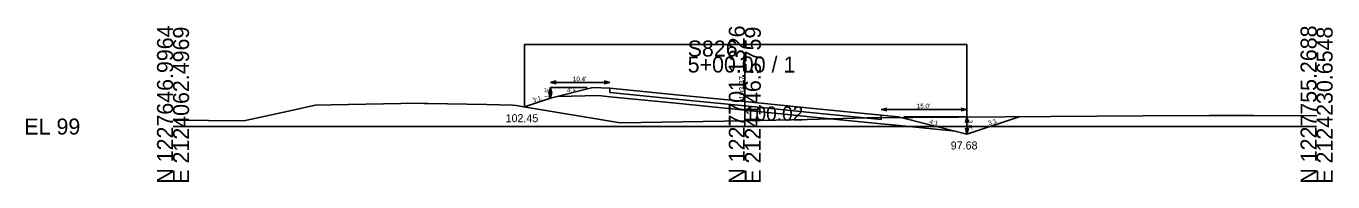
# Model space of a CAD drawing. Extents: x 2118382 to 2129610, y 1213030 to 1222578.
# Drawn here: x 2118381.9 to 2118610.4, y 1215530.1 to 1215557.4 of the extents above; entities that cross this region are included whole.
import ezdxf

# ---------------------------------------------------------------- set-up
doc = ezdxf.new("R2010")
doc.units = 0
for name, color, linetype in [('XS_CELL', 7, 'Continuous'), ('XS_M_DITCH', 7, 'Continuous'), ('XS_P_FINISHED_GRADE', 7, 'Continuous'), ('XS_P_FINISHED_GRADE_ELEV_TX', 7, 'Continuous'), ('XS_P_SUBGRADE_GRANULAR', 7, 'Continuous'), ('XS_P_SUBGRADE_PAVEMENT', 7, 'Continuous'), ('XS_P_TX_CLEARZONE', 7, 'Continuous'), ('XS_P_TX_DCH', 7, 'Continuous'), ('XS_P_TX_FS_BS', 7, 'Continuous'), ('XS_X_GROUND', 7, 'Continuous'), ('XS_X_GROUND_TX', 7, 'Continuous')]:
    doc.layers.add(name, color=color, linetype=linetype)

msp = doc.modelspace()

# ---------------------------------------------------------------- linework, layer by layer
at = {"layer": 'XS_CELL'}
for p, q in [((2118507.6, 1215539.8), (2118507.6, 1215552.06)), ((2118407.6, 1215539.8), (2118507.6, 1215539.8)), ((2118507.6, 1215539.8), (2118607.6, 1215539.8))]:
    msp.add_line(p, q, dxfattribs=at)
at = {"layer": 'XS_M_DITCH'}
for p, q in [((2118469.07, 1215543.26), (2118469.07, 1215554.17)), ((2118469.07, 1215554.17), (2118546.45, 1215554.17)), ((2118546.45, 1215554.17), (2118546.45, 1215538.49))]:
    msp.add_line(p, q, dxfattribs=at)
at = {"layer": 'XS_P_FINISHED_GRADE'}
for p, q in [((2118481.01, 1215546.62), (2118473.59, 1215544.76)), ((2118484.02, 1215546.53), (2118481.01, 1215546.62)), ((2118473.59, 1215544.76), (2118469.07, 1215543.26)), ((2118495.6, 1215545.37), (2118484.02, 1215546.53)), ((2118495.6, 1215545.37), (2118507.6, 1215544.17)), ((2118507.6, 1215544.17), (2118519.6, 1215542.97)), ((2118519.6, 1215542.97), (2118531.42, 1215541.79)), ((2118531.42, 1215541.79), (2118534.43, 1215541.49)), ((2118534.43, 1215541.49), (2118546.45, 1215538.49)), ((2118546.45, 1215538.49), (2118555.56, 1215541.52))]:
    msp.add_line(p, q, dxfattribs=at)
at = {"layer": 'XS_P_SUBGRADE_GRANULAR'}
for p, q in [((2118482.02, 1215545.23), (2118474.88, 1215545.08)), ((2118484.02, 1215545.03), (2118482.02, 1215545.23)), ((2118495.6, 1215543.87), (2118484.02, 1215545.03)), ((2118495.6, 1215543.87), (2118507.6, 1215542.67)), ((2118507.6, 1215542.67), (2118519.6, 1215541.47)), ((2118519.6, 1215541.47), (2118531.42, 1215540.29)), ((2118531.42, 1215540.29), (2118533.42, 1215540.09)), ((2118533.42, 1215540.09), (2118544.46, 1215538.98))]:
    msp.add_line(p, q, dxfattribs=at)
at = {"layer": 'XS_P_SUBGRADE_PAVEMENT'}
for p, q in [((2118484.02, 1215545.78), (2118484.02, 1215546.53)), ((2118495.6, 1215544.62), (2118484.02, 1215545.78)), ((2118495.6, 1215544.62), (2118507.6, 1215543.42)), ((2118507.6, 1215543.42), (2118519.6, 1215542.22)), ((2118519.6, 1215542.22), (2118531.42, 1215541.04)), ((2118531.42, 1215541.04), (2118531.42, 1215541.79))]:
    msp.add_line(p, q, dxfattribs=at)
at = {"layer": 'XS_P_TX_CLEARZONE'}
for p, q in [((2118473.59, 1215546.62), (2118473.34, 1215545.62)), ((2118473.59, 1215547.53), (2118474.59, 1215547.78)), ((2118473.59, 1215547.53), (2118474.59, 1215547.28)), ((2118484.02, 1215547.53), (2118473.59, 1215547.53)), ((2118473.59, 1215546.62), (2118473.84, 1215545.62)), ((2118473.59, 1215546.62), (2118473.59, 1215544.76)), ((2118480.01, 1215546.62), (2118473.59, 1215546.62)), ((2118484.02, 1215547.53), (2118483.02, 1215547.78)), ((2118484.02, 1215547.53), (2118483.02, 1215547.28)), ((2118473.59, 1215544.76), (2118473.34, 1215545.76)), ((2118473.59, 1215544.76), (2118473.84, 1215545.76)), ((2118531.42, 1215542.79), (2118532.43, 1215543.04)), ((2118531.42, 1215542.79), (2118532.43, 1215542.54)), ((2118531.42, 1215542.79), (2118546.45, 1215542.79)), ((2118546.45, 1215542.79), (2118545.45, 1215543.04)), ((2118546.45, 1215542.79), (2118545.45, 1215542.54)), ((2118535.43, 1215541.49), (2118546.45, 1215541.49)), ((2118546.45, 1215541.49), (2118546.2, 1215540.49)), ((2118546.45, 1215541.49), (2118546.45, 1215538.49)), ((2118546.45, 1215541.49), (2118546.7, 1215540.49)), ((2118546.45, 1215538.49), (2118546.2, 1215539.49)), ((2118546.45, 1215538.49), (2118546.7, 1215539.49))]:
    msp.add_line(p, q, dxfattribs=at)
at = {"layer": 'XS_X_GROUND'}
for p, q in [((2118420, 1215540.79), (2118428.32, 1215542.63)), ((2118428.32, 1215542.63), (2118432.47, 1215543.56)), ((2118432.47, 1215543.56), (2118435.25, 1215543.58)), ((2118435.25, 1215543.58), (2118447.44, 1215543.86)), ((2118447.44, 1215543.86), (2118448.52, 1215543.89)), ((2118448.52, 1215543.89), (2118451.57, 1215543.84)), ((2118451.57, 1215543.84), (2118452.19, 1215543.83)), ((2118452.19, 1215543.83), (2118462.48, 1215543.67)), ((2118462.48, 1215543.67), (2118466.97, 1215543.53)), ((2118466.97, 1215543.53), (2118467.62, 1215543.51)), ((2118467.62, 1215543.51), (2118468.96, 1215543.27)), ((2118468.96, 1215543.27), (2118485.78, 1215540.45)), ((2118407.6, 1215540.92), (2118420, 1215540.79)), ((2118485.78, 1215540.45), (2118507.6, 1215540.82)), ((2118507.6, 1215540.82), (2118518.48, 1215541.01)), ((2118518.48, 1215541.01), (2118528.86, 1215541.34)), ((2118528.86, 1215541.34), (2118577.21, 1215541.67)), ((2118577.21, 1215541.67), (2118588.88, 1215541.73)), ((2118588.88, 1215541.73), (2118592.52, 1215541.74)), ((2118592.52, 1215541.74), (2118596.6, 1215541.72)), ((2118596.6, 1215541.72), (2118607.6, 1215541.69))]:
    msp.add_line(p, q, dxfattribs=at)

# ---------------------------------------------------------------- texts
at = {"layer": 'XS_CELL'}
for s, p in [('N 1227646.9964', (2118407.6, 1215529.8)), ('E 2124062.4969', (2118410.4, 1215529.8)), ('N 1227701.1326', (2118507.6, 1215529.8)), ('E 2124146.5759', (2118510.4, 1215529.8)), ('N 1227755.2688', (2118607.6, 1215529.8)), ('E 2124230.6548', (2118610.4, 1215529.8))]:
    msp.add_text(s, height=2.8, rotation=90, dxfattribs=at).set_placement(p)
for s, p in [('S826', (2118497.6, 1215552.06)), ('5+00.00 / 1', (2118497.6, 1215549.26)), ('EL 99', (2118381.6, 1215538.4))]:
    msp.add_text(s, height=2.8, dxfattribs=at).set_placement(p)
at = {"layer": 'XS_P_FINISHED_GRADE_ELEV_TX'}
msp.add_text(' 103.37', height=1, rotation=90, dxfattribs=at).set_placement((2118507.6, 1215544.17))
at = {"layer": 'XS_P_TX_CLEARZONE'}
for s, p in [("10.4'", (2118477.52, 1215547.73)), ("15.0'", (2118537.66, 1215542.99))]:
    msp.add_text(s, height=0.8, dxfattribs=at).set_placement(p)
for s, rotation, p in [("1.9'", 90, (2118473.39, 1215544.8)), ("3.0'", 270, (2118546.65, 1215541.01))]:
    msp.add_text(s, height=0.8, rotation=rotation, dxfattribs=at).set_placement(p)
at = {"layer": 'XS_P_TX_DCH'}
for s, p in [('102.45', (2118465.76, 1215540.56)), ('97.68', (2118543.61, 1215535.79))]:
    msp.add_text(s, height=1.4, dxfattribs=at).set_placement(p)
at = {"layer": 'XS_P_TX_FS_BS'}
for s, rotation, p in [('4:1', 14.0188, (2118476.6, 1215545.72)), ('3:1', 18.4127, (2118470.62, 1215543.99)), ('4:1', 345.9847, (2118539.83, 1215540.35)), ('3:1', 18.4082, (2118550.29, 1215539.98))]:
    msp.add_text(s, height=0.8, rotation=rotation, dxfattribs=at).set_placement(p)
at = {"layer": 'XS_X_GROUND_TX'}
msp.add_text('100.02', height=2.5, dxfattribs=at).set_placement((2118507.6, 1215540.82))

doc.saveas('drawing.dxf')
